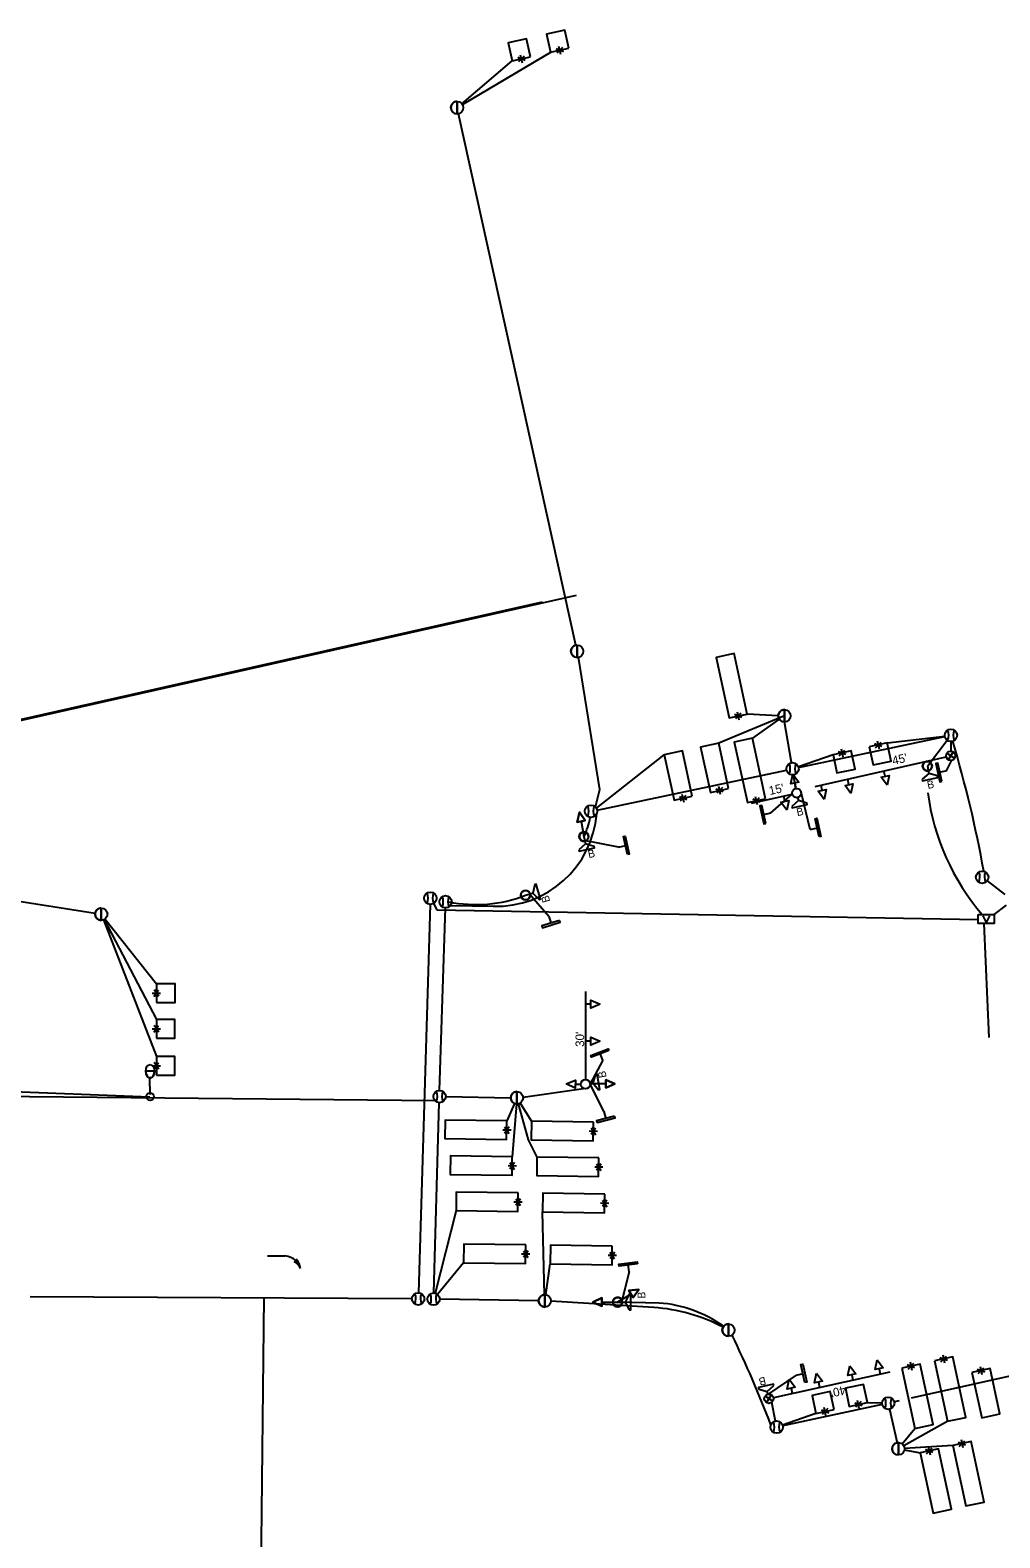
# Model space of a CAD drawing. Extents: x 596176 to 605330, y 332416 to 402398.
# Drawn here: x 604501.7 to 604815.3, y 339222 to 339709.4 of the extents above; entities that cross this region are included whole.
import ezdxf

# ---------------------------------------------------------------- set-up
doc = ezdxf.new("R2010")
doc.units = 0
for name, color, linetype in [('P_LTG', 7, 'Continuous'), ('P_SIG', 7, 'Continuous'), ('P_SIG_Bold', 7, 'Continuous'), ('P_SIG_Conduit', 7, 'Continuous'), ('P_SIG_IC', 7, 'Continuous'), ('P_SIG_Loops', 7, 'Continuous'), ('P_SIG_SignalHeads', 7, 'Continuous')]:
    doc.layers.add(name, color=color, linetype=linetype)

# ---------------------------------------------------------------- blocks, each defined once
blk = doc.blocks.new('_U317')
at = {"layer": 'P_LTG'}
for p, q in [((4.3, 25.1), (-4.1, 25.1)), ((0, 2.3), (0, 18.4))]:
    blk.add_line(p, q, dxfattribs=at)
blk.add_circle((0, 0.1), 3.68, dxfattribs=at)
blk.add_ellipse((0.1, 25.1), major_axis=(0, 6.65), ratio=0.636439, dxfattribs=at)
blk.add_ellipse((0.1, 25.1), major_axis=(0, 6.65), ratio=0.636439, start_param=1.570796, end_param=4.712389, dxfattribs=at)
blk = doc.blocks.new('SIGNAL HEADS and POLES')
at = {"layer": 'P_SIG'}
blk.add_line((-15.4, 0), (0, 0), dxfattribs=at)
for points in [[(-24.4, 0), (-15.4, 4), (-15.4, -4), (-24.4, 0)], [(-15.4, 4), (-24.4, 0), (-15.4, -4), (-15.4, 4)]]:
    blk.add_lwpolyline(points, dxfattribs=at)
blk.add_circle((0, 0), 4.62, dxfattribs=at)
blk.add_circle((0, 0), 4.62, dxfattribs=at)
blk.add_circle((0, 0), 4.62, dxfattribs=at)
for start, end in [(0, 180), (180, 0)]:
    blk.add_arc((0, 0), 4.62, start, end, dxfattribs=at)
blk = doc.blocks.new('_U305')
at = {"layer": 'P_SIG_Loops'}
for p, q in [((-0.055, -0.084), (0.052, 0.081)), ((0.056, -0.083), (-0.053, 0.082)), ((0, 0), (0, -0.229)), ((-0.105, -0.001), (0.099, -0.001))]:
    blk.add_line(p, q, dxfattribs=at)
blk.add_lwpolyline([(0, -0.229), (1.524, -0.229), (1.524, 0.229), (0, 0.229)], close=True, dxfattribs=at)
blk = doc.blocks.new('_U316')
at = {"layer": 'P_SIG_Loops'}
for p, q in [((-0.055, -0.084), (0.052, 0.081)), ((0.056, -0.083), (-0.053, 0.082)), ((0, 0), (0, -0.229)), ((-0.105, -0.001), (0.099, -0.001))]:
    blk.add_line(p, q, dxfattribs=at)
blk.add_lwpolyline([(0, -0.229), (0.457, -0.229), (0.457, 0.229), (0, 0.229)], close=True, dxfattribs=at)
blk = doc.blocks.new('_U309')
at = {"layer": 'P_SIG_Bold'}
for p, q in [((-3.048, 0), (-0.114, 0)), ((-0.081, 0.081), (0.081, -0.081)), ((0.081, 0.081), (-0.081, -0.081))]:
    blk.add_line(p, q, dxfattribs=at)
blk.add_circle((0, 0), 0.114, dxfattribs=at)
blk.add_text("40'", height=0.2134, dxfattribs=at).set_placement((-1.894, 0.092))
blk = doc.blocks.new('_U310')
at = {"layer": 'P_SIG'}
blk.add_circle((0, 0), 4.62, dxfattribs=at)
for start, end in [(0, 180), (180, 0)]:
    blk.add_arc((0, 0), 4.62, start, end, dxfattribs=at)
blk = doc.blocks.new('_U226')
at = {"layer": 'P_SIG'}
blk.add_line((0, 6.1), (0, -6.1), dxfattribs=at)
blk.add_lwpolyline([(0, -6.1), (0, 6.1)], dxfattribs=at)
blk.add_circle((0, 0), 6.1, dxfattribs=at)
for start, end in [(89.7008, 180), (180, 269.7008)]:
    blk.add_arc((0, 0), 6.1, start, end, dxfattribs=at)
blk = doc.blocks.new('_U227')
at = {"layer": 'P_SIG'}
blk.add_circle((0, 0), 6.1, dxfattribs=at)
for centre, start, end in [((-15.5, 0.1), 336.6741, 22.5272), ((15.5, 0.1), 157.5751, 203.4282)]:
    blk.add_arc(centre, 13.3, start, end, dxfattribs=at)
blk = doc.blocks.new('HEAD - TEMPORARY_1')
at = {"layer": 'P_SIG'}
blk.add_line((5.4, 0), (0, 0), dxfattribs=at)
blk.add_lwpolyline([(14.4, 0), (5.4, -4), (5.4, 4)], close=True, dxfattribs=at)
blk = doc.blocks.new('_U318')
at = {"layer": 'P_LTG'}
for p, q in [((4.323, 25.117), (-4.138, 25.117)), ((0.048, 2.299), (0.048, 18.436))]:
    blk.add_line(p, q, dxfattribs=at)
blk.add_ellipse((0.092, 25.117), major_axis=(0, 6.647), ratio=0.636439, dxfattribs=at)
blk.add_ellipse((0.092, 25.117), major_axis=(0, 6.647), ratio=0.636439, start_param=1.570796, end_param=4.712389, dxfattribs=at)
blk = doc.blocks.new('_U319')
at = {"layer": 'P_SIG'}
for p, q in [((-0.675, 0.115), (-0.743, 0.129)), ((-0.725, 0.057), (-0.743, 0.129)), ((-0.017, -0.02), (-0.443, -0.02))]:
    blk.add_line(p, q, dxfattribs=at)
for centre, radius, start, end in [((-0.479, 0.454), 0.392, 205.2667, 239.9151), ((-0.377, 0.361), 0.462, 189.3153, 221.1715), ((-0.412, 0.421), 0.442, 221.4708, 266.0347)]:
    blk.add_arc(centre, radius, start, end, dxfattribs=at)
blk = doc.blocks.new('_U326')
at = {"layer": 'P_SIG_Bold'}
blk.add_line((-91.4, 0), (-4.6, 0), dxfattribs=at)
blk.add_circle((0, 0), 4.57, dxfattribs=at)
blk.add_text("30'", height=8.53, rotation=180.0002, dxfattribs=at).set_placement((-36.8, -1.3))
blk = doc.blocks.new('_U328')
at = {"layer": 'P_SIG'}
blk.add_line((-15.4, 0), (0, 0), dxfattribs=at)
for points in [[(-24.4, 0), (-15.4, 4), (-15.4, -4), (-24.4, 0)], [(-24.4, 0), (-15.4, 4), (-15.4, -4), (-24.4, 0)], [(-15.4, 4), (-24.4, 0), (-15.4, -4), (-15.4, 4)]]:
    blk.add_lwpolyline(points, dxfattribs=at)
blk = doc.blocks.new('_U330')
at = {"layer": 'P_SIG_Bold'}
blk.add_line((-45.7, 0), (-4.6, 0), dxfattribs=at)
blk.add_circle((0, 0), 4.57, dxfattribs=at)
blk.add_text("15'", height=8.53, dxfattribs=at).set_placement((-26.2, 3.7))
blk = doc.blocks.new('_U331')
at = {"layer": 'P_SIG_Loops'}
for p, q in [((-0.055, -0.084), (0.052, 0.081)), ((0.056, -0.083), (-0.053, 0.082)), ((0, 0), (0, -0.229)), ((-0.105, -0.001), (0.099, -0.001))]:
    blk.add_line(p, q, dxfattribs=at)
blk.add_lwpolyline([(0, -0.229), (1.143, -0.229), (1.143, 0.229), (0, 0.229)], close=True, dxfattribs=at)
blk = doc.blocks.new('_U333')
at = {"layer": 'P_SIG_Bold'}
for p, q in [((-3.429, 0), (-0.114, 0)), ((-0.081, 0.081), (0.081, -0.081)), ((0.081, 0.081), (-0.081, -0.081))]:
    blk.add_line(p, q, dxfattribs=at)
blk.add_circle((0, 0), 0.114, dxfattribs=at)
blk.add_text("45'", height=0.2134, dxfattribs=at).set_placement((-1.432, 0.092))
blk = doc.blocks.new('_U223')
at = {"layer": 'P_SIG'}
blk.add_circle((0, 0), 6.1, dxfattribs=at)
for centre, start, end in [((-15.5, 0.1), 336.6741, 22.5272), ((15.5, 0.1), 157.5751, 203.4282)]:
    blk.add_arc(centre, 13.3, start, end, dxfattribs=at)
blk = doc.blocks.new('COMMUNICATION VAULT')
at = {"layer": 'P_SIG'}
for p in [(-1.61, 1.65), (1.56, 1.65)]:
    blk.add_line(p, (-0.03, -1.65), dxfattribs=at)
blk.add_lwpolyline([(-3.98, 2.22), (3.98, 2.22), (3.98, -2.22), (-3.98, -2.22)], close=True, dxfattribs=at)

msp = doc.modelspace()

# ---------------------------------------------------------------- linework, layer by layer
at = {"layer": 'P_SIG'}
for p, q in [((604791.87, 339471.51), (604792.38, 339469.17)), ((604798.11, 339469.97), (604799.75, 339473.4)), ((604798.11, 339469.97), (604795.77, 339469.46)), ((604741.19, 339456.31), (604748.15, 339462.39)), ((604754.01, 339451.05), (604751.11, 339463.04)), ((604749.93, 339461.35), (604750.15, 339460.37)), ((604749.93, 339461.35), (604750.15, 339460.37)), ((604741.19, 339456.31), (604738.85, 339455.79)), ((604680.81, 339448.71), (604681.33, 339446.36)), ((604692.03, 339445.3), (604681.04, 339447.48)), ((604754.01, 339451.05), (604756.36, 339451.57)), ((604692.03, 339445.3), (604694.38, 339445.81)), ((604661.96, 339429.74), (604664.27, 339430.41)), ((604669.44, 339422.92), (604663.14, 339430.17)), ((604524.7, 339425.64), (604524.68, 339421.64)), ((604669.44, 339422.92), (604670.16, 339420.64)), ((604686.94, 339376.41), (604686.08, 339378.65)), ((604686.94, 339376.41), (604682.8, 339368.82)), ((604682.78, 339368.95), (604683.67, 339369.11)), ((604687.29, 339359.82), (604682.8, 339368.82)), ((604687.29, 339359.82), (604687.89, 339357.5)), ((604695.46, 339308.03), (604695.16, 339310.41)), ((604695.46, 339308.03), (604692.95, 339298.25)), ((604691.7, 339298.25), (604694.11, 339298.26)), ((604749.44, 339274.64), (604740.34, 339268.47)), ((604749.44, 339274.64), (604751.78, 339275.15)), ((604740.31, 339268.47), (604740.11, 339269.35))]:
    msp.add_line(p, q, dxfattribs=at)
for points in [[(604796.54, 339466.6), (604795.25, 339472.46), (604794.66, 339472.33), (604795.95, 339466.47)], [(604790.24, 339467.28), (604790.35, 339466.78), (604795.24, 339467.85), (604795.12, 339468.36), (604792.38, 339469.17)], [(604739.61, 339452.93), (604738.32, 339458.79), (604737.74, 339458.66), (604739.03, 339452.8)], [(604748, 339458.49), (604748.11, 339457.98), (604753, 339459.06), (604752.89, 339459.57), (604750.15, 339460.37)], [(604756.86, 339448.65), (604755.57, 339454.51), (604756.15, 339454.64), (604757.45, 339448.78)], [(604694.88, 339442.9), (604693.59, 339448.76), (604694.17, 339448.89), (604695.47, 339443.03)], [(604679.18, 339444.48), (604679.3, 339443.97), (604684.18, 339445.05), (604684.07, 339445.56), (604681.33, 339446.36)], [(604666.28, 339428.38), (604666.78, 339428.52), (604665.4, 339433.33), (604664.9, 339433.19), (604664.27, 339430.4)], [(604672.94, 339421.65), (604667.22, 339419.85), (604667.4, 339419.28), (604673.12, 339421.08)], [(604688.88, 339379.59), (604683.29, 339377.42), (604683.07, 339377.98), (604688.67, 339380.15)], [(604685.48, 339366.9), (604685.99, 339367), (604685.07, 339371.92), (604684.56, 339371.82), (604683.67, 339369.11)], [(604690.72, 339358.37), (604684.91, 339356.87), (604685.06, 339356.29), (604690.87, 339357.79)], [(604698.11, 339310.65), (604692.15, 339309.9), (604692.08, 339310.5), (604698.03, 339311.24)], [(604695.48, 339295.76), (604696, 339295.76), (604696, 339300.76), (604695.48, 339300.76), (604694.1, 339298.26)], [(604752.29, 339272.24), (604750.99, 339278.1), (604751.58, 339278.22), (604752.87, 339272.36)], [(604742.24, 339271.24), (604742.12, 339271.75), (604737.24, 339270.64), (604737.36, 339270.13), (604740.11, 339269.35)]]:
    msp.add_lwpolyline(points, close=True, dxfattribs=at)
for points in [[(604790.24, 339467.28), (604790.35, 339466.78), (604795.24, 339467.85), (604795.12, 339468.36), (604792.38, 339469.17), (604790.24, 339467.28)], [(604748, 339458.49), (604748.11, 339457.98), (604753, 339459.06), (604752.89, 339459.57), (604750.15, 339460.37), (604748, 339458.49)], [(604679.18, 339444.48), (604679.3, 339443.97), (604684.18, 339445.05), (604684.07, 339445.56), (604681.33, 339446.36), (604679.18, 339444.48)], [(604666.28, 339428.38), (604666.78, 339428.52), (604665.4, 339433.33), (604664.9, 339433.19), (604664.27, 339430.4), (604666.28, 339428.38)], [(604524.68, 339421.64), (604524.7, 339425.64)], [(604685.48, 339366.9), (604685.99, 339367), (604685.07, 339371.92), (604684.56, 339371.82), (604683.67, 339369.11), (604685.48, 339366.9)], [(604695.48, 339295.76), (604696, 339295.76), (604696, 339300.76), (604695.48, 339300.76), (604694.1, 339298.26), (604695.48, 339295.76)], [(604742.24, 339271.24), (604742.12, 339271.75), (604737.24, 339270.64), (604737.36, 339270.13), (604740.11, 339269.35), (604742.24, 339271.24)]]:
    msp.add_lwpolyline(points, dxfattribs=at)
msp.add_circle((604524.69, 339423.64), 2, dxfattribs=at)
for start, end in [(89.7008, 180), (180, 269.7008)]:
    msp.add_arc((604524.69, 339423.64), 2, start, end, dxfattribs=at)
at = {"layer": 'P_SIG_Conduit'}
for p, q in [((604747.93, 339472.63), (604745.64, 339485.79)), ((604791.87, 339471.51), (604798.27, 339479.89)), ((604749.38, 339464.3), (604748.61, 339468.68)), ((604634.12, 339366.68), (604636, 339425.66)), ((604459, 339367.75), (604540.44, 339364.59)), ((604636.12, 339364.65), (604657.14, 339364.31)), ((604661.13, 339364.51), (604680.7, 339367.3)), ((604632.21, 339301.2), (604634, 339362.69)), ((604666.14, 339298.66), (604634.15, 339299.17)), ((604779.65, 339263.6), (604782.07, 339252.77))]:
    msp.add_line(p, q, dxfattribs=at)
for points in [[(604678.15, 339510.58), (604640.21, 339682.44)], [(604684.52, 339458.34), (604685.94, 339463.96), (604679.02, 339506.68)], [(604750.23, 339471.06), (604797.53, 339481.06)], [(604799.46, 339479.47), (604799.43, 339476.36)], [(604685.07, 339457.27), (604746.32, 339470.23)], [(604460.93, 339433.64), (604522.77, 339423.92)], [(604811.19, 339434.38), (604816.98, 339430.02)], [(604637.63, 339426.43), (604651.48, 339426.19)], [(604632.71, 339363.27), (604490.54, 339364.68), (604479.27, 339364.49)], [(604703.39, 339296.47), (604670.14, 339298.51)], [(604705.12, 339297.93), (604691.9, 339298.22)], [(604849.09, 339281.03), (604786.69, 339267.21)], [(604742.76, 339259.79), (604741.56, 339265.82)], [(604777.26, 339265.16), (604745.11, 339258.25)], [(604782.78, 339266.35), (604781.17, 339266)]]:
    msp.add_lwpolyline(points, dxfattribs=at)
for centre, radius, start, end in [((604436.12, 339370.24), 380.01, 10.1969, 16.719), ((604652.49, 339458.73), 32.55, 268.2192, 355.5038), ((604659.71, 339459.01), 23.49, 333.9623, 350.0353), ((604645.84, 339471.78), 45.02, 258.7415, 290.9796), ((604699.58, 339240.2), 56.4, 62.3143, 86.1247), ((604702.35, 339257.55), 40.47, 54.3067, 86.0731), ((604425.66, 339139.11), 337.45, 20.7234, 26.0982)]:
    msp.add_arc(centre, radius, start, end, dxfattribs=at)
at = {"layer": 'P_SIG_IC'}
for p, q in [((604631.06, 339426.82), (604627.25, 339301.28)), ((604633.19, 339425.06), (604808.3, 339421.87)), ((604811.83, 339383.8), (604810.27, 339420.58))]:
    msp.add_line(p, q, dxfattribs=at)
for points in [[(604632.12, 339427.07), (604633.19, 339425.06)], [(604817.37, 339426.53), (604813.34, 339423.49)], [(604625.19, 339299.29), (604501.7, 339299.9)]]:
    msp.add_lwpolyline(points, dxfattribs=at)
msp.add_arc((604867.42, 339473.01), 76.1, 187.6486, 220.5893, dxfattribs=at)
at = {"layer": 'P_SIG_Loops'}
for p, q in [((604641.5, 339685.41), (604670.05, 339702.28)), ((604641.33, 339685.65), (604657.64, 339699.5)), ((604745.65, 339487.79), (604724.43, 339478.95)), ((604733.63, 339488.36), (604743.65, 339487.89)), ((604744, 339486.66), (604735.32, 339480.54)), ((604778.95, 339479.01), (604797.5, 339481.24)), ((604684.86, 339457.89), (604706.78, 339475.14)), ((604761.38, 339475.16), (604750.16, 339471.3)), ((604525.41, 339421.77), (604542.53, 339377.59)), ((604525.62, 339421.87), (604542.53, 339389.6)), ((604525.93, 339422.07), (604542.57, 339401.1)), ((604541.2, 339398.08), (604543.88, 339398.09)), ((604541.85, 339397), (604543.26, 339399.17)), ((604543.31, 339397.01), (604541.88, 339399.18)), ((604542.57, 339398.1), (604542.58, 339395.1)), ((604541.16, 339386.58), (604543.84, 339386.58)), ((604541.81, 339385.49), (604543.22, 339387.67)), ((604543.27, 339385.51), (604541.83, 339387.68)), ((604542.53, 339386.6), (604542.53, 339383.6)), ((604541.16, 339374.57), (604543.84, 339374.58)), ((604541.81, 339373.49), (604543.22, 339375.66)), ((604543.27, 339373.5), (604541.83, 339375.67)), ((604542.53, 339374.59), (604542.53, 339371.59)), ((604658.34, 339362.45), (604655.88, 339356.81)), ((604658.98, 339362.29), (604657.63, 339345.23)), ((604662.88, 339350.68), (604659.67, 339362.35)), ((604660.2, 339362.59), (604663.88, 339356.7)), ((604665.63, 339345.12), (604662.88, 339350.68)), ((604639.44, 339327.82), (604632.66, 339301.14)), ((604668.09, 339300.63), (604667.44, 339327.42)), ((604641.9, 339310.98), (604633.44, 339300.74)), ((604668.43, 339300.61), (604669.9, 339310.58)), ((604755.86, 339262.22), (604745.04, 339258.48)), ((604772.5, 339265.77), (604777.22, 339265.62)), ((604783.77, 339252.36), (604787.86, 339257.36)), ((604798.45, 339259.69), (604784.25, 339251.79)), ((604800.14, 339251.87), (604784.5, 339250.93)), ((604784.47, 339250.46), (604789.55, 339249.54))]:
    msp.add_line(p, q, dxfattribs=at)
for points in [[(604542.58, 339395.1), (604548.58, 339395.11), (604548.57, 339401.11), (604542.57, 339401.1)], [(604542.53, 339383.6), (604548.53, 339383.6), (604548.53, 339389.6), (604542.53, 339389.6)], [(604542.53, 339371.59), (604548.53, 339371.6), (604548.53, 339377.6), (604542.53, 339377.59)]]:
    msp.add_lwpolyline(points, close=True, dxfattribs=at)

# ---------------------------------------------------------------- block references
at = {"layer": 'P_SIG'}
for name, p, xscale, yscale, rotation in [('_U318', (604696.9, 339530.5), 13.123333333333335, 13.123333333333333, 102.6891845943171), ('_U318', (604707.83, 339532.72), 13.123333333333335, 13.123333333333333, 102.6891845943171), ('_U333', (604799.42, 339474.86), 13.123333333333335, 13.123333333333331, 12.8291215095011), ('_U310', (604791.87, 339471.51), 0.32808333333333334, 0.32808333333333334, -79.47535112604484), ('_U330', (604749.61, 339462.81), 0.32808333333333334, 0.3280833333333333, 12.461291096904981), ('SIGNAL HEADS and POLES', (604680.81, 339448.71), 0.32808333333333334, 0.32808333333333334, -79.47535112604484), ('_U310', (604661.94, 339429.81), 0.32808333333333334, 0.32808333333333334, 180), ('_U326', (604681.31, 339368.67), 0.3280833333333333, 0.3280833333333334, -90.00022331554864), ('_U317', (604540.49, 339364.63), 0.3280833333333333, 0.32808333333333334, 0.28242094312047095), ('_U328', (604682.8, 339368.82), 0.32808333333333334, 0.32808333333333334, 180), ('_U319', (604578.27, 339312.98), 13.123333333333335, 13.123333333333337, 179.35577875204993), ('SIGNAL HEADS and POLES', (604691.7, 339298.25), 0.32808333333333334, 0.3280833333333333, -149.23830530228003), ('_U318', (604578.27, 339329.91), 13.123333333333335, 13.123333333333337, 179.35577875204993), ('_U309', (604740.64, 339267), 13.123333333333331, 13.123333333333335, -167.5414512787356)]:
    msp.add_blockref(name, p, dxfattribs=dict(at, xscale=xscale, yscale=yscale, rotation=rotation))
at = {"layer": 'P_SIG', "xscale": 0.32808333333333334, "yscale": 0.32808333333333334}
msp.add_blockref('SIGNAL HEADS and POLES', (604691.7, 339298.25), dxfattribs=at)
at = {"layer": 'P_SIG_Conduit', "xscale": 0.32808333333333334, "yscale": 0.32808333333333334}
for name, p in [('_U226', (604639.78, 339684.39)), ('_U226', (604678.59, 339508.63)), ('_U226', (604745.65, 339487.79)), ('_U227', (604799.49, 339481.47)), ('_U227', (604748.27, 339470.65)), ('_U227', (604683.1, 339456.93)), ('_U227', (604809.6, 339435.58)), ('_U227', (604636.05, 339427.65)), ('_U227', (604634.12, 339364.68)), ('_U226', (604659.14, 339364.28)), ('_U227', (604632.16, 339299.2)), ('_U226', (604668.14, 339298.63)), ('_U226', (604727.54, 339289.18)), ('_U227', (604779.22, 339265.55)), ('_U227', (604743.15, 339257.82)), ('_U226', (604782.5, 339250.81))]:
    msp.add_blockref(name, p, dxfattribs=at)
at = {"layer": 'P_SIG_IC'}
for name, p, xscale, yscale in [('_U223', (604631.14, 339428.81), 0.32808333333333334, 0.32808333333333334), ('COMMUNICATION VAULT', (604810.91, 339422.04), 0.6561666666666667, 0.6561666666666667), ('_U223', (604627.19, 339299.28), 0.32808333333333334, 0.32808333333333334)]:
    msp.add_blockref(name, p, dxfattribs=dict(at, xscale=xscale, yscale=yscale))
at = {"layer": 'P_SIG_Loops'}
for name, p, xscale, yscale, rotation in [('_U316', (604660.58, 339700.13), 13.123333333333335, 13.123333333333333, 102.56641830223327), ('_U316', (604672.98, 339702.93), 13.123333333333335, 13.123333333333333, 102.56641830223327), ('_U305', (604730.69, 339487.72), 13.123333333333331, 13.123333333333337, 102.18605092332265), ('_U331', (604712.88, 339461.11), 13.123333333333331, 13.123333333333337, 102.18605092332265), ('_U331', (604724.66, 339463.66), 13.123333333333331, 13.123333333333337, 102.18605092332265), ('_U305', (604736.6, 339460.35), 13.123333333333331, 13.123333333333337, 102.18605092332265), ('_U316', (604764.31, 339475.79), 13.123333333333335, 13.123333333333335, -77.81394907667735), ('_U316', (604775.99, 339478.37), 13.123333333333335, 13.123333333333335, -77.81394907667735), ('_U305', (604655.84, 339353.81), 13.12333333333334, 13.12333333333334, 179.19388611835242), ('_U305', (604683.83, 339353.42), 13.12333333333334, 13.12333333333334, 179.19388611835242), ('_U305', (604657.59, 339342.23), 13.12333333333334, 13.12333333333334, 179.19388611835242), ('_U305', (604685.58, 339341.84), 13.12333333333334, 13.12333333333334, 179.19388611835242), ('_U305', (604659.48, 339330.54), 13.123333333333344, 13.123333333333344, 179.19388611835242), ('_U305', (604687.48, 339330.14), 13.123333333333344, 13.123333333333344, 179.19388611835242), ('_U305', (604661.94, 339313.7), 13.123333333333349, 13.123333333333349, 179.19388611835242), ('_U305', (604689.94, 339313.3), 13.123333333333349, 13.123333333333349, 179.19388611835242), ('_U305', (604797.16, 339279.87), 13.123333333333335, 13.123333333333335, -77.81394907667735), ('_U305', (604786.58, 339277.54), 13.123333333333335, 13.123333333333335, -77.81394907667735), ('_U331', (604809.23, 339276.11), 13.123333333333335, 13.123333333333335, -77.81394907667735), ('_U316', (604769.57, 339265.13), 13.123333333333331, 13.123333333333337, 102.18605092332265), ('_U316', (604758.79, 339262.85), 13.123333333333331, 13.123333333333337, 102.18605092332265), ('_U305', (604792.49, 339250.17), 13.123333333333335, 13.123333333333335, -77.81394907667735), ('_U305', (604803.07, 339252.51), 13.123333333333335, 13.123333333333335, -77.81394907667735)]:
    msp.add_blockref(name, p, dxfattribs=dict(at, xscale=xscale, yscale=yscale, rotation=rotation))
at = {"layer": 'P_SIG_SignalHeads'}
for p, xscale, yscale, rotation in [((604749.38, 339464.3), 0.3280833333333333, 0.3280833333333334, 102.30178657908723), ((604766.15, 339467.23), 0.3280833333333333, 0.3280833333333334, -77.69821342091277), ((604777.85, 339469.97), 0.3280833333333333, 0.3280833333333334, -77.69821342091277), ((604745.41, 339461.89), 0.3280833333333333, 0.3280833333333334, -77.69821342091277), ((604757.48, 339465.37), 0.3280833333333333, 0.3280833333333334, -77.69821342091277), ((604679.81, 339368.67), 0.32808333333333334, 0.3280833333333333, 179.08348304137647), ((604767.8, 339273.01), 0.32808333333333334, 0.3280833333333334, 102.30178657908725), ((604776.66, 339274.96), 0.32808333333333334, 0.3280833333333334, 102.30178657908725), ((604748.2, 339268.67), 0.32808333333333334, 0.3280833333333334, 102.30178657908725), ((604757.04, 339270.63), 0.32808333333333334, 0.3280833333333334, 102.30178657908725)]:
    msp.add_blockref('HEAD - TEMPORARY_1', p, dxfattribs=dict(at, xscale=xscale, yscale=yscale, rotation=rotation))
at = {"layer": 'P_SIG_SignalHeads', "xscale": 0.32808333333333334, "yscale": 0.32808333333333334}
for p in [(604681.31, 339394.57), (604681.31, 339382.59)]:
    msp.add_blockref('HEAD - TEMPORARY_1', p, dxfattribs=at)

# ---------------------------------------------------------------- texts
at = {"layer": 'P_SIG'}
for rotation, p in [(12.4446, (604792.08, 339464.11)), (12.4446, (604749.84, 339455.32)), (12.4446, (604682.39, 339441.75)), (106.0637, (604669.92, 339427.8)), (100.5576, (604688.15, 339370.94)), (90.0968, (604700.67, 339299.35)), (192.8589, (604739.34, 339274.12))]:
    msp.add_text('B', height=2.52, rotation=rotation, dxfattribs=at).set_placement(p)

doc.saveas('drawing.dxf')
